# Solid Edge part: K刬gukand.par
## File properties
Author: Türk
Template: Iso Part.par
Last saved by: Türk
Revision: 7
Application: Solid Edge
Accuracy: 0,990
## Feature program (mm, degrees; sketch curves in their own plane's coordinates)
thread "unnamed Thread 1"
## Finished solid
Body 1: solid body, 22 faces, 55 edges, 34 vertices.
  Faces by surface: plane 15, cylinder 7
  Edges by curve: line 39, circle 14, ellipse 2
Bounding box of the edges (mm): 100.000 x 14.500 x 385.000, from (-50, 0, -50) to (50, 14.5, 335).
Cylindrical faces by radius (mm): R5 x2, R10 x1, R25 x1, R60 x1, R120 x1, R200 x1
Planar faces by outward normal: +x 1, +y 1, +z 2, -x 1, -y 1, -z 1, oblique 8
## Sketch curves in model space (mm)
line (50, 0, 0) -> (0, 0, 0)
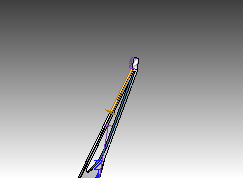
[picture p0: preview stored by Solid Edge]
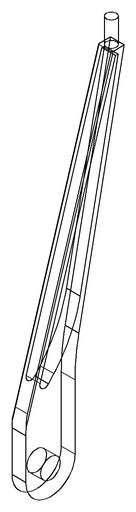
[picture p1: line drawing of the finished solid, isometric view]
